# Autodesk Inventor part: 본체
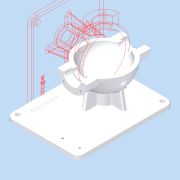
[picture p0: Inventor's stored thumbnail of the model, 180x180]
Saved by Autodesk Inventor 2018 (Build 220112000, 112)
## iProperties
Created: 2015-12
Part Number: 본체
Material: 알루미늄 6061
Document SubType Name: Modeling
Designer: mduedu
Density: 2.71 g/cm^3
Mass: 1330.63 g
Surface Area: 1128.56 cm^2
Volume: 491.008 cm^3
Appearance: 알루미늄 - 평지
Author: mduedu
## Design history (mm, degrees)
sketch "스케치1"
  geometry: L1 (-53, 0)-(53, 0); A1 r 53 centre (0, 0) between (53, 0) and (-53, 0); 2 further points
  constraints: 2 coincident, 2 end point, 2 point on circle, 1 centre point, 1 horizontal, 1 midpoint
  dimensions: "d0" = 53 radius of A1
revolve "회전1" sketch "스케치1" stored, may be unused: angle "d2" = 90 deg
feature "쉘1" dims "d11" = 8
node "작업 평면1"
sketch "스케치2"
  geometry: C1 r 31 at (0, 0); 1 further point
  constraints: 1 centre point, 1 coincident
  dimensions: "d4" = 62 diameter of C1
extrude "돌출1" join sketch "스케치2" stored distance "d5" = 10; taper "d6" = 0 deg
hole "구멍1" diameter "d14" = 35; stored, may be unused: countersink angle "d18" = 90 deg, drill point angle "d20" = 0 deg; dims "d12" = 10, "d13" = 10, "d15" = 6, "d16" = 4, "d17" = 2, "d19" = 16
hole "구멍2" diameter "d23" = 27; stored, may be unused: countersink angle "d27" = 90 deg, drill point angle "d29" = 0 deg; dims "d21" = 10, "d22" = 10, "d24" = 6, "d25" = 4, "d26" = 2, "d28" = 16
fillet "모깎기1" dims "d30" = 0.3
chamfer "모따기1" distance "d40" = 1; stored, may be unused: second distance "d41" = 2, angle "d42" = 45 deg
sketch "스케치4"
  geometry: L1 (0, 0)-(0, -25); L2 (0, 0)-(-17.678, -17.678); A1 r 25 centre (0, 0) between (-17.678, -17.678) and (0, -25); 1 further point
  constraints: 4 end point, 2 point on circle, 1 centre point, 1 coincident, 1 vertical
  dimensions: "d43" = 50 diameter of A1; "d47" = 45 deg angle of L1 L2
hole "구멍4" sketch "스케치4" at (-17.678, -17.678) diameter "d49" = 3.242; stored, may be unused: countersink angle "d53" = 90 deg, drill point angle "d55" = 118 deg; dims "d50" = 11, "d51" = 4, "d52" = 2, "d54" = 13
node "작업 평면3"
sketch "스케치6" dims "d21" = 10, "d22" = 10
  geometry: L1 (-70, -75)-(130, -75); L2 (130, -75)-(130, 76); L3 (130, 76)-(-70, 76); L4 (-70, 76)-(-70, -75); 2 further points
  constraints: 8 end point, 2 parallel, 1 coincident, 1 horizontal, 1 perpendicular
  dimensions: "d158" = 200 distance of L3.end L2.end; "d159" = 151 distance of L2.end L1.end; "d162" = 75 distance from line of L1 point (0, 0); "d163" = 70 distance from line of L4 point (0, 0)
extrude "돌출3" join sketch "스케치6" distance "d80" = 10; taper "d81" = 0 deg
sketch "스케치7"
  geometry: C1 r 20 at (0, 0); 2 further points
  constraints: 2 coincident, 1 centre point
  dimensions: "d82" = 40 diameter of C1
extrude "돌출4" join sketch "스케치7" stored distance "d84" = 10; taper "d85" = 0 deg
sketch "스케치8"
  geometry: 3 further points
  constraints: 2 coincident
hole "구멍6" sketch "스케치8" at (0, 0) diameter "d86" = 20; stored, may be unused: countersink angle "d90" = 90 deg, drill point angle "d92" = 118 deg; dims "d87" = 7, "d88" = 40, "d89" = 5, "d91" = 10
fillet "모깎기2" dims "d93" = 0.3
sketch "스케치9"
  geometry: L1 (-45, -75)-(-38.245, -36.692); L2 (70, -75)-(-130, -75) reference; A1 r 53 centre (0, 0) between (42.988, 31) and (42.988, -31) reference; 1 further point
  constraints: 2 end point, 1 coincident, 1 point on circle, 1 point on line
  dimensions: "d94" = 45 horizontal distance of L1.start point (0, 0); "d160" = 80 deg angle of L2 L1
feature "리브1" sketch "스케치9" dims "d96" = 1, "d97" = 8, "d98" = 0, "d99" = 0, "d100" = 1, "d101" = 1
fillet "모깎기3" dims "d120" = 3
fillet "모깎기4" dims "d121" = 3, "d122" = 3
fillet "모깎기5" dims "d123" = 3
sketch "스케치12"
  geometry: L1 (0, 100)-(0, -100); L2 (0, 100)-(100, 100); L3 (100, 100)-(100, -100); L4 (100, -100)-(0, -100); 2 further points
  constraints: 8 end point, 3 perpendicular, 1 coincident, 1 midpoint, 1 vertical
  dimensions: "d127" = 200 distance of L2.end L3.end; "d129" = 100 distance between parallel lines of L1 L3
extrude "돌출5" cut sketch "스케치12" extent not by distance; stored distance "d130" = 10; taper "d131" = 0 deg
fillet "모깎기10" dims "d164" = 12
fillet "모깎기11" dims "d165" = 3
sketch "스케치15"
  geometry: C1 r 4.5 at (-118, 63); C2 r 4.5 at (58, 63); C3 r 4.5 at (58, -64); A1 r 12 centre (-118, 63) between (-118, 75) and (-130, 63) reference; A2 r 12 centre (58, 63) between (70, 63) and (58, 75) reference; A3 r 12 centre (58, -64) between (58, -76) and (70, -64) reference; 1 further point
  constraints: 3 centre point, 3 coincident, 2 equal radius
  dimensions: "d166" = 9 diameter of C1
extrude "돌출8" cut sketch "스케치15" extent not by distance; stored distance "d167" = 10; taper "d168" = 0 deg
sketch "스케치16"
  geometry: L1 (-130, 63)-(-130, -64) reference; L2 (-118, -76)-(58, -76) reference; 2 further points
  constraints: 1 other
  dimensions: "d169" = 60 distance from line of point (-70, 54) L1; "d170" = 130 distance from line of point (-70, 54) L2
feature "엠보싱2" sketch "스케치16" dims "d171" = 0.5, "d172" = 0
sketch "스케치17"
  geometry: L1 (-118, 76)-(58, 76) reference; L2 (-130, -63)-(-130, 64) reference; 2 further points
  constraints: 1 vertical alignment
  dimensions: "d180" = 13 distance from line of L1 point (-114, 63); "d181" = 16 distance from line of point (-114, 63) L2; "d182" = 36 distance of point (-114, 27) point (-114, 63)
hole "구멍9" sketch "스케치17" at (-114, 63), (-114, 27) diameter "d173" = 3.242; stored, may be unused: countersink angle "d177" = 90 deg, drill point angle "d179" = 0 deg; dims "d174" = 6, "d175" = 4, "d176" = 2, "d178" = 8
node "솔리드1"
mirror "대칭1"
mirror "대칭2"
pattern_circular "원형 패턴1" dims angle "d57" = 360 deg
mirror "대칭3"
pattern_circular "원형 패턴3" dims angle "d103" = 360 deg
other parameters: "d3" = 67, "d77" = -85
